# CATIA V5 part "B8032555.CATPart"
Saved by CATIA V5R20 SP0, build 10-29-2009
Part number: B8032555
Revision: 5
Definition: design
Nomenclature: B8032555
Source: made
Description: NOT SPECIFIED
Bounding box of the stored display mesh (mm): x -20 to 20, y -20 to 20, z 0 to 55
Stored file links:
  C:\Users\Utente\Desktop\3D files B803\B8032555.CATPart
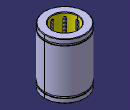
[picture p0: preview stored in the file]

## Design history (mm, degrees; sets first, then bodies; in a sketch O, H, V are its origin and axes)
Body1 "MANIFOLD_SOLID_BREP #38" (main body)
  Solid1: solid without history
Body2 "MANIFOLD_SOLID_BREP #76"
  Solid2: solid without history
Body3 "MANIFOLD_SOLID_BREP #114"
  Solid3: solid without history
Body4 "MANIFOLD_SOLID_BREP #152"
  Solid4: solid without history
Body5 "MANIFOLD_SOLID_BREP #190"
  Solid5: solid without history
Body6 "MANIFOLD_SOLID_BREP #228"
  Solid6: solid without history
Body7 "MANIFOLD_SOLID_BREP #266"
  Solid7: solid without history
Body8 "MANIFOLD_SOLID_BREP #304"
  Solid8: solid without history
Body9 "MANIFOLD_SOLID_BREP #2424"
  Solid9: solid without history
Body10 "MANIFOLD_SOLID_BREP #2462"
  Solid10: solid without history
Body11 "MANIFOLD_SOLID_BREP #2500"
  Solid11: solid without history
Body12 "MANIFOLD_SOLID_BREP #2538"
  Solid12: solid without history
Body13 "MANIFOLD_SOLID_BREP #2576"
  Solid13: solid without history
Body14 "MANIFOLD_SOLID_BREP #2614"
  Solid14: solid without history
Body15 "MANIFOLD_SOLID_BREP #2652"
  Solid15: solid without history
Body16 "MANIFOLD_SOLID_BREP #2690"
  Solid16: solid without history
Body17 "MANIFOLD_SOLID_BREP #2728"
  Solid17: solid without history
Body18 "MANIFOLD_SOLID_BREP #2766"
  Solid18: solid without history
Body19 "MANIFOLD_SOLID_BREP #2804"
  Solid19: solid without history
Body20 "MANIFOLD_SOLID_BREP #2842"
  Solid20: solid without history
Body21 "MANIFOLD_SOLID_BREP #2880"
  Solid21: solid without history
Body22 "MANIFOLD_SOLID_BREP #2918"
  Solid22: solid without history
Body23 "MANIFOLD_SOLID_BREP #2956"
  Solid23: solid without history
Body24 "MANIFOLD_SOLID_BREP #2994"
  Solid24: solid without history
Body25 "MANIFOLD_SOLID_BREP #3032"
  Solid25: solid without history
Body26 "MANIFOLD_SOLID_BREP #3070"
  Solid26: solid without history
Body27 "MANIFOLD_SOLID_BREP #3108"
  Solid27: solid without history
Body28 "MANIFOLD_SOLID_BREP #3146"
  Solid28: solid without history
Body29 "MANIFOLD_SOLID_BREP #3184"
  Solid29: solid without history
Body30 "MANIFOLD_SOLID_BREP #3222"
  Solid30: solid without history
Body31 "MANIFOLD_SOLID_BREP #3260"
  Solid31: solid without history
Body32 "MANIFOLD_SOLID_BREP #3298"
  Solid32: solid without history
Body33 "MANIFOLD_SOLID_BREP #3336"
  Solid33: solid without history
Body34 "MANIFOLD_SOLID_BREP #3374"
  Solid34: solid without history
Body35 "MANIFOLD_SOLID_BREP #3412"
  Solid35: solid without history
Body36 "MANIFOLD_SOLID_BREP #3450"
  Solid36: solid without history
Body37 "MANIFOLD_SOLID_BREP #3488"
  Solid37: solid without history
Body38 "MANIFOLD_SOLID_BREP #3526"
  Solid38: solid without history
Body39 "MANIFOLD_SOLID_BREP #3564"
  Solid39: solid without history
Body40 "MANIFOLD_SOLID_BREP #3602"
  Solid40: solid without history
Body41 "MANIFOLD_SOLID_BREP #3640"
  Solid41: solid without history
Body42 "MANIFOLD_SOLID_BREP #3678"
  Solid42: solid without history
Body43 "MANIFOLD_SOLID_BREP #3716"
  Solid43: solid without history
Body44 "MANIFOLD_SOLID_BREP #3754"
  Solid44: solid without history
Body45 "MANIFOLD_SOLID_BREP #3792"
  Solid45: solid without history
Body46 "MANIFOLD_SOLID_BREP #3830"
  Solid46: solid without history
Body47 "MANIFOLD_SOLID_BREP #3868"
  Solid47: solid without history
Body48 "MANIFOLD_SOLID_BREP #3906"
  Solid48: solid without history
Body49 "MANIFOLD_SOLID_BREP #3944"
  Solid49: solid without history
Body50 "MANIFOLD_SOLID_BREP #3982"
  Solid50: solid without history
Body51 "MANIFOLD_SOLID_BREP #4020"
  Solid51: solid without history
Body52 "MANIFOLD_SOLID_BREP #4058"
  Solid52: solid without history
Body53 "MANIFOLD_SOLID_BREP #4096"
  Solid53: solid without history
Body54 "MANIFOLD_SOLID_BREP #4134"
  Solid54: solid without history
Body55 "MANIFOLD_SOLID_BREP #4172"
  Solid55: solid without history
Body56 "MANIFOLD_SOLID_BREP #4210"
  Solid56: solid without history
Body57 "MANIFOLD_SOLID_BREP #4248"
  Solid57: solid without history
Body58 "MANIFOLD_SOLID_BREP #4286"
  Solid58: solid without history
Body59 "MANIFOLD_SOLID_BREP #4324"
  Solid59: solid without history
Body60 "MANIFOLD_SOLID_BREP #4362"
  Solid60: solid without history
Body61 "MANIFOLD_SOLID_BREP #4400"
  Solid61: solid without history
Body62 "MANIFOLD_SOLID_BREP #4438"
  Solid62: solid without history
Body63 "MANIFOLD_SOLID_BREP #4476"
  Solid63: solid without history
Body64 "MANIFOLD_SOLID_BREP #4514"
  Solid64: solid without history
Body65 "MANIFOLD_SOLID_BREP #4552"
  Solid65: solid without history
Body66 "MANIFOLD_SOLID_BREP #4590"
  Solid66: solid without history
Body67 "MANIFOLD_SOLID_BREP #4628"
  Solid67: solid without history
Body68 "MANIFOLD_SOLID_BREP #4666"
  Solid68: solid without history
Body69 "MANIFOLD_SOLID_BREP #4704"
  Solid69: solid without history
Body70 "MANIFOLD_SOLID_BREP #4742"
  Solid70: solid without history
Body71 "MANIFOLD_SOLID_BREP #4780"
  Solid71: solid without history
Body72 "MANIFOLD_SOLID_BREP #4818"
  Solid72: solid without history
Body73 "MANIFOLD_SOLID_BREP #4856"
  Solid73: solid without history
Body74 "MANIFOLD_SOLID_BREP #4894"
  Solid74: solid without history
Body75 "MANIFOLD_SOLID_BREP #4932"
  Solid75: solid without history
Body76 "MANIFOLD_SOLID_BREP #4970"
  Solid76: solid without history
Body77 "MANIFOLD_SOLID_BREP #5008"
  Solid77: solid without history
Body78 "MANIFOLD_SOLID_BREP #5046"
  Solid78: solid without history
Body79 "MANIFOLD_SOLID_BREP #5084"
  Solid79: solid without history
Body80 "MANIFOLD_SOLID_BREP #5122"
  Solid80: solid without history
Body81 "MANIFOLD_SOLID_BREP #5160"
  Solid81: solid without history
Body82 "MANIFOLD_SOLID_BREP #5198"
  Solid82: solid without history
Body83 "MANIFOLD_SOLID_BREP #5236"
  Solid83: solid without history
Body84 "MANIFOLD_SOLID_BREP #5274"
  Solid84: solid without history
Body85 "MANIFOLD_SOLID_BREP #5312"
  Solid85: solid without history
Body86 "MANIFOLD_SOLID_BREP #5350"
  Solid86: solid without history
Body87 "MANIFOLD_SOLID_BREP #5388"
  Solid87: solid without history
Body88 "MANIFOLD_SOLID_BREP #5426"
  Solid88: solid without history
Body89 "MANIFOLD_SOLID_BREP #5464"
  Solid89: solid without history
Body90 "MANIFOLD_SOLID_BREP #5502"
  Solid90: solid without history
Body91 "MANIFOLD_SOLID_BREP #5540"
  Solid91: solid without history
Body92 "MANIFOLD_SOLID_BREP #5578"
  Solid92: solid without history
Body93 "MANIFOLD_SOLID_BREP #5616"
  Solid93: solid without history
Body94 "MANIFOLD_SOLID_BREP #5654"
  Solid94: solid without history
Body95 "MANIFOLD_SOLID_BREP #5692"
  Solid95: solid without history
Body96 "MANIFOLD_SOLID_BREP #5730"
  Solid96: solid without history
Body97 "MANIFOLD_SOLID_BREP #5768"
  Solid97: solid without history
Body98 "MANIFOLD_SOLID_BREP #5806"
  Solid98: solid without history
Body99 "MANIFOLD_SOLID_BREP #5844"
  Solid99: solid without history
Body100 "MANIFOLD_SOLID_BREP #5882"
  Solid100: solid without history
Body101 "MANIFOLD_SOLID_BREP #5920"
  Solid101: solid without history
Body102 "MANIFOLD_SOLID_BREP #5958"
  Solid102: solid without history
Body103 "MANIFOLD_SOLID_BREP #5996"
  Solid103: solid without history
Body104 "MANIFOLD_SOLID_BREP #6034"
  Solid104: solid without history
Body105 "MANIFOLD_SOLID_BREP #6072"
  Solid105: solid without history
Body106 "MANIFOLD_SOLID_BREP #6110"
  Solid106: solid without history
Body107 "MANIFOLD_SOLID_BREP #6148"
  Solid107: solid without history
Body108 "MANIFOLD_SOLID_BREP #6186"
  Solid108: solid without history
Body109 "MANIFOLD_SOLID_BREP #6224"
  Solid109: solid without history
Body110 "MANIFOLD_SOLID_BREP #6262"
  Solid110: solid without history
Body111 "MANIFOLD_SOLID_BREP #6300"
  Solid111: solid without history
Body112 "MANIFOLD_SOLID_BREP #6338"
  Solid112: solid without history
Body113 "MANIFOLD_SOLID_BREP #6376"
  Solid113: solid without history
Body114 "MANIFOLD_SOLID_BREP #6414"
  Solid114: solid without history
Body115 "MANIFOLD_SOLID_BREP #6452"
  Solid115: solid without history
Body116 "MANIFOLD_SOLID_BREP #6490"
  Solid116: solid without history
Body117 "MANIFOLD_SOLID_BREP #6528"
  Solid117: solid without history
Body118 "MANIFOLD_SOLID_BREP #6566"
  Solid118: solid without history
Body119 "MANIFOLD_SOLID_BREP #6604"
  Solid119: solid without history
Body120 "MANIFOLD_SOLID_BREP #6642"
  Solid120: solid without history
Body121 "MANIFOLD_SOLID_BREP #6680"
  Solid121: solid without history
